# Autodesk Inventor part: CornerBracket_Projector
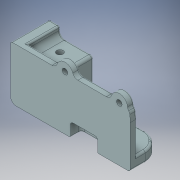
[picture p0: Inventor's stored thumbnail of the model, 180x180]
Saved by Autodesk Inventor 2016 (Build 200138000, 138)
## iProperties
Created: 2016-01
Part Number: CornerBracket_Projector
Material: Generic
Document SubType Name: Modeling
Designer: John
Density: 1 g/cm^3
Appearance: Default
Author: John
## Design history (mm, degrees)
feature "SOLID1"
node "Direct Edit1"
sketch "Sketch1"
  geometry: L1 (-130.161, 62.523)-(77.311, 62.523); L2 (77.311, 62.523)-(77.311, -68.836); L3 (77.311, -68.836)-(-130.161, -68.836); L4 (-130.161, -68.836)-(-130.161, 62.523); 1 further point
  constraints: 8 end point, 2 parallel, 1 horizontal, 1 perpendicular
extrude "Extrusion1" cut sketch "Sketch1" stored distance "d6" = 0; taper "d7" = 0 deg
sketch "Sketch2"
  geometry: L1 (32.919, 36.4)-(32.919, 10) reference; L2 (59.319, 36.4)-(32.919, 36.4) reference; L3 (59.319, 10)-(59.319, 36.4) reference; L4 (32.919, 10)-(59.319, 10) reference; L5 (0, 10)-(23.919, 10) reference; L6 (-2.935, 2)-(-2.935, 8) reference; L7 (64.319, 0)-(0, 0) reference; L8 (69.319, 47.5)-(69.319, 5) reference; L9 (60.819, 49)-(67.819, 49) reference; L10 (59.319, 45.4)-(59.319, 47.5) reference; L11 (31.419, 40.4)-(54.319, 40.4) reference; L12 (28.919, 15)-(28.919, 37.9) reference; L13 (33.219, 36.1)-(33.219, 10.3); L14 (33.219, 10.3)-(59.019, 10.3); L15 (59.019, 10.3)-(59.019, 36.1); L16 (59.019, 36.1)-(33.219, 36.1); A1 r 5 centre (64.319, 5) between (64.319, 0) and (69.319, 5) reference; A2 r 1.5 centre (67.819, 47.5) between (69.319, 47.5) and (67.819, 49) reference; A3 r 1.5 centre (60.819, 47.5) between (60.819, 49) and (59.319, 47.5) reference; A4 r 5 centre (54.319, 45.4) between (54.319, 40.4) and (59.319, 45.4) reference; A5 r 2.5 centre (31.419, 37.9) between (31.419, 40.4) and (28.919, 37.9) reference; A6 r 5 centre (23.919, 15) between (23.919, 10) and (28.919, 15) reference; 1 further point
  constraints: 8 end point, 5 other
  dimensions: "d8" = 25.8 distance of L15.end L13.start
extrude "Extrusion2" join sketch "Sketch2" stored distance "d9" = 10; taper "d10" = 0 deg
sketch "Sketch3"
  geometry: C1 r 3 at (0, 0) reference; 1 further point
extrude "Extrusion3" cut sketch "Sketch3" distance "d11" = 10; taper "d12" = 0 deg
sketch "Sketch4"
  geometry: L1 (25, 0)-(25, 22.9) reference; L2 (25, 22.9)-(0, 22.9) reference; L3 (0, 22.9)-(0, 0) reference; L4 (0, 0)-(25, 0) reference; C1 r 3 at (11.6, 7.7) reference; 1 further point
extrude "Extrusion4" cut sketch "Sketch4" distance "d13" = 10; taper "d14" = 0 deg
fillet "Fillet1" dims "d15" = 2
body "Solid1"
node "Projected Loop1"
node "Projected Loop2"
node "Projected Loop3"
move_body "Move1" dims "d2" = -20
move_body "Move2" dims "d4" = 8
other parameters: "d0" = 0, "d1" = 0, "d3" = 0, "d5" = 0
